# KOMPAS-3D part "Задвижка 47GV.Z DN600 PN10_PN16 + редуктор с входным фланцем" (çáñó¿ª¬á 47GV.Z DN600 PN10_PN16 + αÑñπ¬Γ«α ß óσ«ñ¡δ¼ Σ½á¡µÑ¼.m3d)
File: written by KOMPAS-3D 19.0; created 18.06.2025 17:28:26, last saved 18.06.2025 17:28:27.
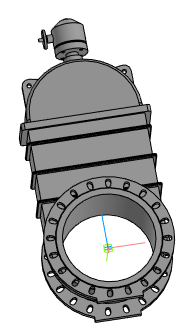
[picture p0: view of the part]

Document properties: Полное имя файла: Задвижка 47GV.Z DN600 PN10_PN16 + редуктор с входным валом.a3d

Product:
- Part/product: Задвижка 47GV.Z DN600 PN10_PN16 + редуктор с входным фланцем
    Масса: 1778.01
  - Body: Тело 1
      Масса: 1778.3

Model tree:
1. Операция без истории:1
